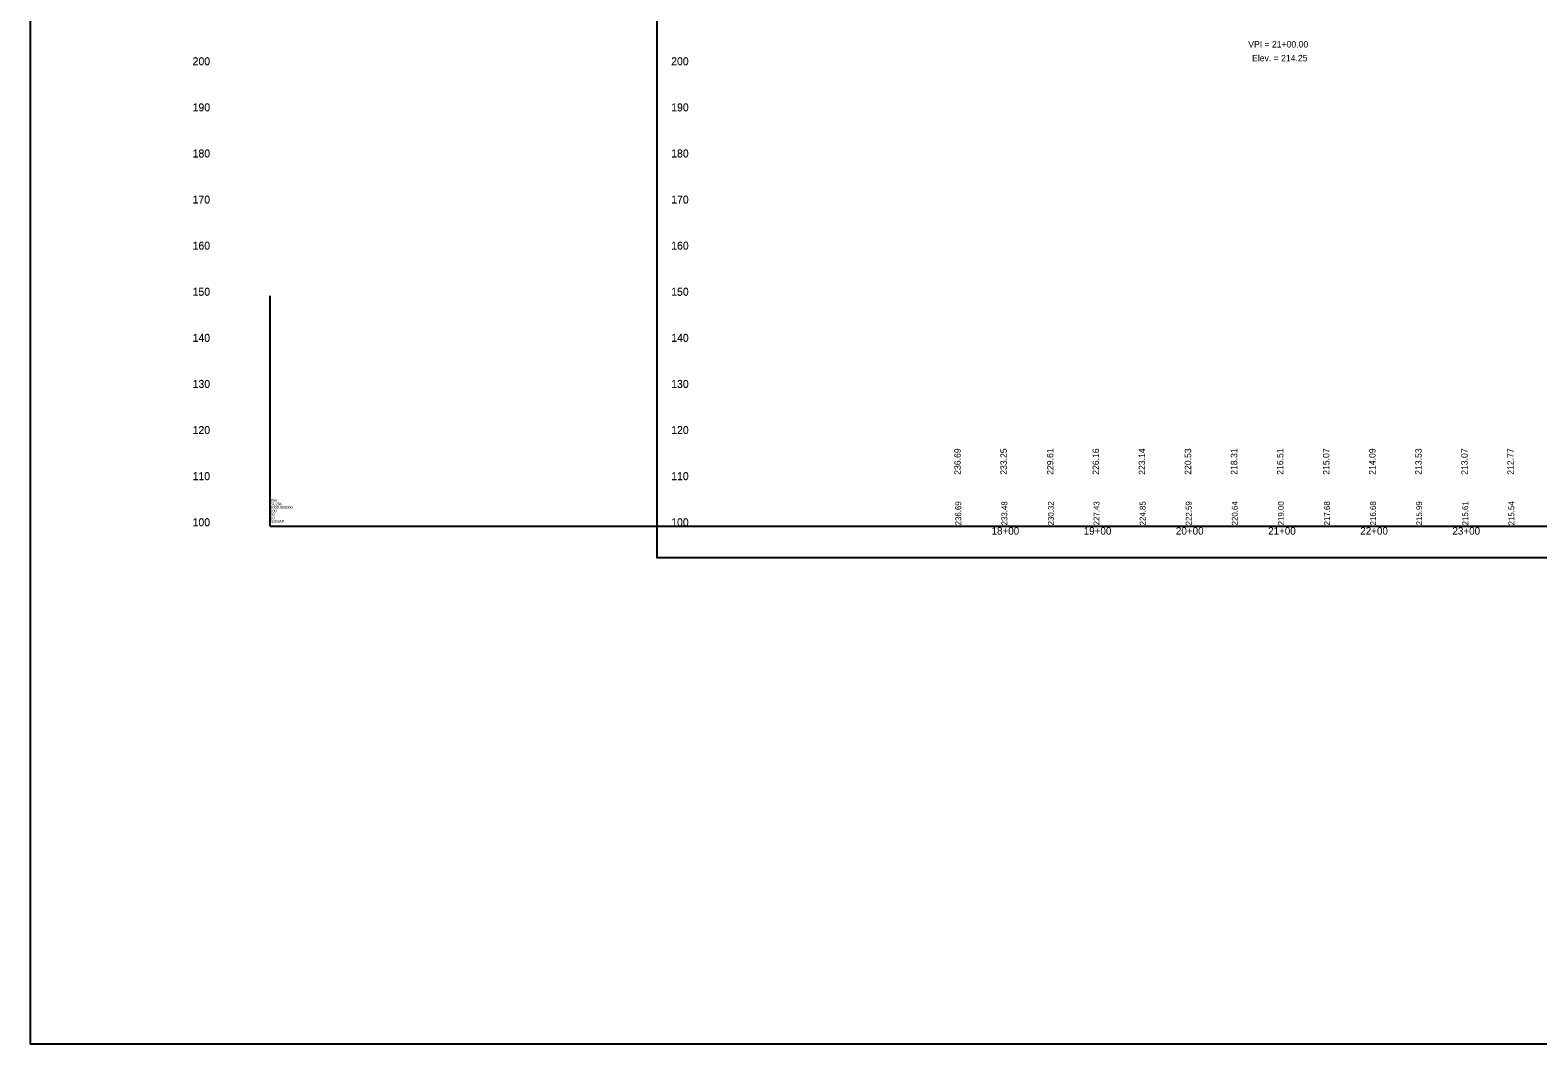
# Model space of a CAD drawing. Extents: x 2224795 to 2228395, y 930927 to 933127.
# Drawn here: x 2224795 to 2226430, y 930927 to 932027 of the extents above; entities that cross this region are included whole.
import ezdxf

# ---------------------------------------------------------------- set-up
doc = ezdxf.new("R2010")
doc.units = 0
for name, color, linetype in [('RD_DDB_ElevTX', 7, 'Continuous'), ('RD_DDB_Profile_Lbl', 7, 'Continuous'), ('RD_DDB_StaTX', 7, 'Continuous'), ('RD_DDB_StripGrade', 7, 'Continuous'), ('RD_GPK_Profile_Cell', 7, 'Continuous'), ('RD_SHT_IplotShp', 7, 'Continuous'), ('RD_SHT_ShtClip', 7, 'Continuous')]:
    doc.layers.add(name, color=color, linetype=linetype)

msp = doc.modelspace()

# ---------------------------------------------------------------- linework, layer by layer
at = {"layer": 'RD_GPK_Profile_Cell'}
for q in [(2225055.1, 931738.5), (2228134, 931488.5), (2225055.1, 931488.5)]:
    msp.add_line((2225055.1, 931488.5), q, dxfattribs=at)
at = {"layer": 'RD_SHT_IplotShp'}
msp.add_lwpolyline([(2228394.5, 933127.2), (2224794.5, 933127.2), (2224794.5, 930927.2), (2228394.5, 930927.2)], close=True, dxfattribs=at)
at = {"layer": 'RD_SHT_ShtClip'}
msp.add_lwpolyline([(2225474.6, 932554.3), (2227274.6, 932554.3), (2227274.6, 931454.3), (2225474.6, 931454.3)], close=True, dxfattribs=at)

# ---------------------------------------------------------------- texts
at = {"layer": 'RD_DDB_ElevTX'}
for s, p in [('200', (2224970.8, 931988.8)), ('200', (2224970.8, 931988.5)), ('200', (2225490, 931988.8)), ('200', (2225490, 931988.5)), ('190', (2224970.8, 931938.8)), ('190', (2224970.8, 931938.5)), ('190', (2225490, 931938.8)), ('190', (2225490, 931938.5)), ('180', (2224970.8, 931888.8)), ('180', (2224970.8, 931888.5)), ('180', (2225490, 931888.8)), ('180', (2225490, 931888.5)), ('170', (2224970.8, 931838.8)), ('170', (2224970.8, 931838.5)), ('170', (2225490, 931838.8)), ('170', (2225490, 931838.5)), ('160', (2224970.8, 931788.8)), ('160', (2224970.8, 931788.5)), ('160', (2225490, 931788.8)), ('160', (2225490, 931788.5)), ('150', (2224970.8, 931738.8)), ('150', (2224970.8, 931738.5)), ('150', (2225490, 931738.8)), ('150', (2225490, 931738.5)), ('140', (2224970.8, 931688.8)), ('140', (2224970.8, 931688.5)), ('140', (2225490, 931688.8)), ('140', (2225490, 931688.5)), ('130', (2224970.8, 931638.8)), ('130', (2224970.8, 931638.5)), ('130', (2225490, 931638.8)), ('130', (2225490, 931638.5)), ('120', (2224970.8, 931588.8)), ('120', (2224970.8, 931588.5)), ('120', (2225490, 931588.8)), ('120', (2225490, 931588.5)), ('110', (2224970.8, 931538.8)), ('110', (2224970.8, 931538.5)), ('110', (2225490, 931538.8)), ('110', (2225490, 931538.5)), ('100', (2224970.8, 931488.8)), ('100', (2224970.8, 931488.5)), ('100', (2225490, 931488.8)), ('100', (2225490, 931488.5))]:
    msp.add_text(s, height=8.5, dxfattribs=at).set_placement(p)
at = {"layer": 'RD_DDB_Profile_Lbl'}
for s, p in [('VPI = 21+00.00', (2226116, 932007.8)), ('Elev. = 214.25', (2226120.2, 931992.8))]:
    msp.add_text(s, height=7, dxfattribs=at).set_placement(p)
at = {"layer": 'RD_DDB_StaTX'}
for s, p in [('18+00', (2225837.5, 931479.5)), ('19+00', (2225937.5, 931479.5)), ('20+00', (2226037.5, 931479.5)), ('21+00', (2226137.5, 931479.5)), ('22+00', (2226237.5, 931479.5)), ('23+00', (2226337.5, 931479.5))]:
    msp.add_text(s, height=8, dxfattribs=at).set_placement(p)
at = {"layer": 'RD_DDB_StripGrade'}
for s, height, p in [('236.69', 7, (2225804.1, 931544.4)), ('233.25', 7, (2225854.1, 931544.4)), ('229.61', 7, (2225904.6, 931544.4)), ('226.16', 7, (2225954.1, 931544.4)), ('223.14', 7, (2226004.1, 931544.4)), ('220.53', 7, (2226054.1, 931544.4)), ('218.31', 7, (2226104.1, 931544.4)), ('216.51', 7, (2226154.1, 931544.4)), ('215.07', 7, (2226204.1, 931544.4)), ('214.09', 7, (2226254.1, 931544.4)), ('213.53', 7, (2226304.1, 931544.4)), ('213.07', 7, (2226354.1, 931544.4)), ('212.77', 7, (2226404.1, 931544.4)), ('236.69', 6.4, (2225804.6, 931489.5)), ('233.48', 6.4, (2225854.6, 931489.5)), ('230.32', 6.4, (2225905.1, 931489.5)), ('227.43', 6.4, (2225954.6, 931489.5)), ('224.85', 6.4, (2226004.6, 931489.5)), ('222.59', 6.4, (2226054.6, 931489.5)), ('220.64', 6.4, (2226104.6, 931489.5)), ('219.00', 6.4, (2226154.6, 931489.5)), ('217.68', 6.4, (2226204.6, 931489.5)), ('216.68', 6.4, (2226254.6, 931489.5)), ('215.99', 6.4, (2226304.6, 931489.5)), ('215.61', 6.4, (2226354.6, 931489.5)), ('215.54', 6.4, (2226404.6, 931489.5))]:
    msp.add_text(s, height=height, rotation=90, dxfattribs=at).set_placement(p)
at = {"layer": 'RD_GPK_Profile_Cell'}
for s, p in [('SC296', (2225055.1, 931511.3)), ('296', (2225055.1, 931515.1)), ('50', (2225055.1, 931499.9)), ('1000.000000', (2225055.1, 931507.5)), ('100', (2225055.1, 931503.7)), ('10', (2225055.1, 931496.1)), ('NOGAP', (2225055.1, 931492.3))]:
    msp.add_text(s, height=3, dxfattribs=at).set_placement(p)

doc.saveas('drawing.dxf')
